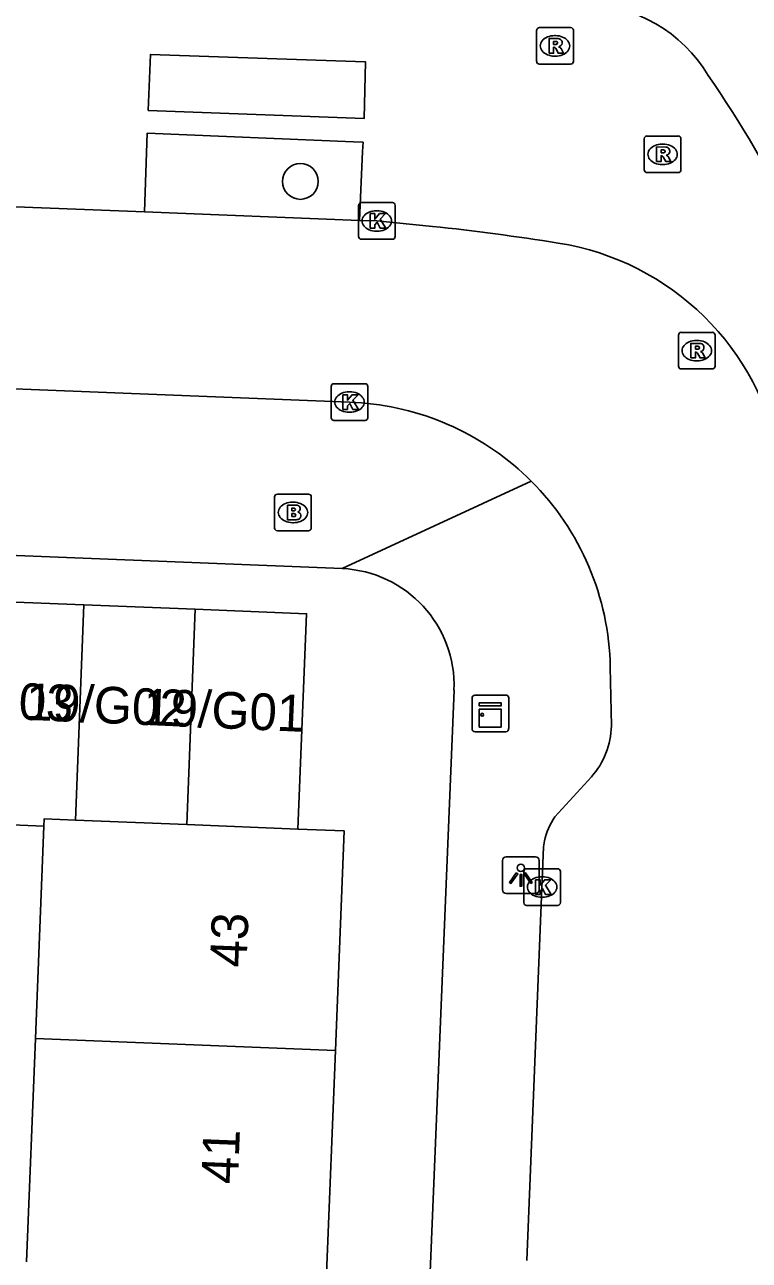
# Model space of a CAD drawing. Extents: x 161355 to 162026, y 386504 to 387459.
# Drawn here: x 161623.15 to 161642.93, y 387194.48 to 387228.21 of the extents above; entities that cross this region are included whole.
import ezdxf

# ---------------------------------------------------------------- set-up
doc = ezdxf.new("R2010")
doc.units = 0
for name, color, linetype in [('IMGEO_Boom', 7, 'Continuous'), ('IMGEO_Brandkraan', 7, 'Continuous'), ('IMGEO_Kast', 7, 'Continuous'), ('IMGEO_Kolk', 7, 'Continuous'), ('IMGEO_Lichtpunt', 7, 'Continuous'), ('IMGEO_Pand', 7, 'Continuous'), ('IMGEO_Pand_nummerreeks', 7, 'Continuous'), ('IMGEO_Rijbaan_lokaal_open', 7, 'Continuous'), ('IMGEO_Rioolput', 7, 'Continuous'), ('IMGEO_Voetpad_open', 7, 'Continuous')]:
    doc.layers.add(name, color=color, linetype=linetype)

msp = doc.modelspace()

# ---------------------------------------------------------------- linework, layer by layer
at = {"layer": 'IMGEO_Boom'}
msp.add_circle((161630.678, 387223.931), 0.489, dxfattribs=at)
at = {"layer": 'IMGEO_Brandkraan'}
for p, q in [((161629.976, 387214.47), (161629.976, 387215.322)), ((161630.051, 387215.396), (161630.903, 387215.396)), ((161630.464, 387215.176), (161630.489, 387215.176)), ((161630.977, 387215.322), (161630.977, 387214.47)), ((161630.487, 387214.616), (161630.462, 387214.616)), ((161630.903, 387214.396), (161630.051, 387214.396))]:
    msp.add_line(p, q, dxfattribs=at)
for points in [[(161629.976, 387214.47), (161629.976, 387215.322)], [(161630.051, 387215.396), (161630.903, 387215.396)], [(161630.977, 387215.322), (161630.977, 387214.47)], [(161630.324, 387215.096), (161630.324, 387214.696), (161630.537, 387214.696)], [(161630.555, 387215.096), (161630.324, 387215.096)], [(161630.503, 387215.015), (161630.449, 387215.015), (161630.449, 387214.939)], [(161630.449, 387214.939), (161630.502, 387214.939)], [(161630.511, 387214.863), (161630.449, 387214.863), (161630.449, 387214.782)], [(161630.449, 387214.782), (161630.511, 387214.782)], [(161630.903, 387214.396), (161630.051, 387214.396)]]:
    msp.add_lwpolyline(points, dxfattribs=at)
for centre, radius, start, end in [((161630.053, 387215.32), 0.0765, 91.552, 178.448), ((161630.053, 387215.32), 0.0765, 91.552, 178.448), ((161630.901, 387215.32), 0.0765, 1.552, 88.448), ((161630.901, 387215.32), 0.0765, 1.552, 88.448), ((161630.504, 387214.977), 0.0379, 267.8285, 90.9355), ((161630.512, 387214.822), 0.0404, 269.8759, 90.5077), ((161630.559, 387214.951), 0.145, 59.4692, 91.5367), ((161630.584, 387214.998), 0.0922, 285.5137, 58.1501), ((161630.589, 387214.806), 0.105, 301.3115, 78.989), ((161630.053, 387214.472), 0.0765, 181.552, 268.448), ((161630.053, 387214.472), 0.0765, 181.552, 268.448), ((161630.543, 387214.947), 0.251, 268.6676, 293.5347), ((161630.901, 387214.472), 0.0765, 271.552, 358.448), ((161630.901, 387214.472), 0.0765, 271.552, 358.448)]:
    msp.add_arc(centre, radius, start, end, dxfattribs=at)
for centre, major_axis, ratio, start_param, end_param in [((161630.463, 387214.896), (-0.387, 0.002), 0.722429, 4.712389, 7.853982), ((161630.488, 387214.896), (-0.39, 0.002), 0.717154, 1.570796, 4.712389)]:
    msp.add_ellipse(centre, major_axis=major_axis, ratio=ratio, start_param=start_param, end_param=end_param, dxfattribs=at)
at = {"layer": 'IMGEO_Kast'}
for p, q in [((161635.364, 387208.987), (161635.364, 387209.828)), ((161635.364, 387209.828), (161635.364, 387208.987)), ((161635.439, 387209.912), (161636.28, 387209.912)), ((161636.28, 387209.912), (161635.439, 387209.912)), ((161636.364, 387209.837), (161636.364, 387208.996)), ((161636.364, 387208.996), (161636.364, 387209.837)), ((161636.289, 387208.912), (161635.448, 387208.912)), ((161635.448, 387208.912), (161636.289, 387208.912))]:
    msp.add_line(p, q, dxfattribs=at)
for points in [[(161635.559, 387209.702), (161636.159, 387209.702), (161636.159, 387209.617), (161635.559, 387209.617), (161635.559, 387209.702)], [(161635.559, 387209.527), (161636.159, 387209.527), (161636.159, 387209.038), (161635.559, 387209.038), (161635.559, 387209.527)]]:
    msp.add_lwpolyline(points, dxfattribs=at)
msp.add_circle((161635.643, 387209.376), 0.0377, dxfattribs=at)
for centre, start, end in [((161635.442, 387209.834), 92.4484, 184.2845), ((161635.442, 387209.834), 92.4484, 184.2845), ((161636.286, 387209.834), 2.4484, 94.2845), ((161636.286, 387209.834), 2.4484, 94.2845), ((161635.442, 387208.99), 182.4484, 274.2845), ((161635.442, 387208.99), 182.4484, 274.2845), ((161636.286, 387208.99), 272.4484, 4.2845), ((161636.286, 387208.99), 272.4484, 4.2845)]:
    msp.add_arc(centre, 0.0779, start, end, dxfattribs=at)
at = {"layer": 'IMGEO_Kolk'}
for p, q in [((161632.265, 387222.426), (161632.265, 387223.278)), ((161632.34, 387223.352), (161633.192, 387223.352)), ((161633.266, 387223.278), (161633.266, 387222.426)), ((161632.753, 387223.132), (161632.778, 387223.132)), ((161632.776, 387222.572), (161632.751, 387222.572)), ((161633.192, 387222.352), (161632.34, 387222.352)), ((161631.518, 387217.483), (161631.518, 387218.335)), ((161631.593, 387218.409), (161632.445, 387218.409)), ((161632.006, 387218.189), (161632.031, 387218.189)), ((161632.519, 387218.335), (161632.519, 387217.483)), ((161632.029, 387217.629), (161632.004, 387217.629)), ((161632.445, 387217.409), (161631.593, 387217.409)), ((161636.776, 387204.246), (161636.776, 387205.098)), ((161636.851, 387205.172), (161637.703, 387205.172)), ((161637.777, 387205.098), (161637.777, 387204.246)), ((161637.264, 387204.952), (161637.289, 387204.952)), ((161637.287, 387204.392), (161637.262, 387204.392)), ((161637.703, 387204.172), (161636.851, 387204.172))]:
    msp.add_line(p, q, dxfattribs=at)
for points in [[(161632.265, 387222.426), (161632.265, 387223.278)], [(161632.34, 387223.352), (161633.192, 387223.352)], [(161633.266, 387223.278), (161633.266, 387222.426)], [(161632.586, 387223.052), (161632.709, 387223.052), (161632.709, 387222.901), (161632.839, 387223.052), (161633.003, 387223.052), (161632.857, 387222.901), (161633.01, 387222.652), (161632.858, 387222.652), (161632.773, 387222.816), (161632.709, 387222.749), (161632.709, 387222.652), (161632.586, 387222.652), (161632.586, 387223.052)], [(161633.192, 387222.352), (161632.34, 387222.352)], [(161631.518, 387217.483), (161631.518, 387218.335)], [(161631.593, 387218.409), (161632.445, 387218.409)], [(161632.519, 387218.335), (161632.519, 387217.483)], [(161631.839, 387218.109), (161631.962, 387218.109), (161631.962, 387217.958), (161632.092, 387218.109), (161632.256, 387218.109), (161632.11, 387217.958), (161632.263, 387217.709), (161632.111, 387217.709), (161632.026, 387217.873), (161631.962, 387217.806), (161631.962, 387217.709), (161631.839, 387217.709), (161631.839, 387218.109)], [(161632.445, 387217.409), (161631.593, 387217.409)], [(161636.776, 387204.246), (161636.776, 387205.098)], [(161636.851, 387205.172), (161637.703, 387205.172)], [(161637.777, 387205.098), (161637.777, 387204.246)], [(161637.097, 387204.872), (161637.22, 387204.872), (161637.22, 387204.721), (161637.35, 387204.872), (161637.514, 387204.872), (161637.368, 387204.721), (161637.521, 387204.472), (161637.369, 387204.472), (161637.284, 387204.636), (161637.22, 387204.569), (161637.22, 387204.472), (161637.097, 387204.472), (161637.097, 387204.872)], [(161637.703, 387204.172), (161636.851, 387204.172)]]:
    msp.add_lwpolyline(points, dxfattribs=at)
for centre, start, end in [((161632.342, 387223.276), 91.552, 178.448), ((161632.342, 387223.276), 91.552, 178.448), ((161633.19, 387223.276), 1.552, 88.448), ((161633.19, 387223.276), 1.552, 88.448), ((161632.342, 387222.428), 181.552, 268.448), ((161632.342, 387222.428), 181.552, 268.448), ((161633.19, 387222.428), 271.552, 358.448), ((161633.19, 387222.428), 271.552, 358.448), ((161631.595, 387218.333), 91.552, 178.448), ((161631.595, 387218.333), 91.552, 178.448), ((161632.443, 387218.333), 1.552, 88.448), ((161632.443, 387218.333), 1.552, 88.448), ((161631.595, 387217.485), 181.552, 268.448), ((161631.595, 387217.485), 181.552, 268.448), ((161632.443, 387217.485), 271.552, 358.448), ((161632.443, 387217.485), 271.552, 358.448), ((161636.853, 387205.096), 91.552, 178.448), ((161636.853, 387205.096), 91.552, 178.448), ((161637.701, 387205.096), 1.552, 88.448), ((161637.701, 387205.096), 1.552, 88.448), ((161636.853, 387204.248), 181.552, 268.448), ((161636.853, 387204.248), 181.552, 268.448), ((161637.701, 387204.248), 271.552, 358.448), ((161637.701, 387204.248), 271.552, 358.448)]:
    msp.add_arc(centre, 0.0765, start, end, dxfattribs=at)
for centre, major_axis, ratio, start_param, end_param in [((161632.752, 387222.852), (-0.387, 0.002), 0.722429, 4.712389, 7.853982), ((161632.777, 387222.852), (-0.39, 0.002), 0.717154, 1.570796, 4.712389), ((161632.005, 387217.909), (-0.387, 0.002), 0.722429, 4.712389, 7.853982), ((161632.03, 387217.909), (-0.39, 0.002), 0.717154, 1.570796, 4.712389), ((161637.263, 387204.672), (-0.387, 0.002), 0.722429, 4.712389, 7.853982), ((161637.288, 387204.672), (-0.39, 0.002), 0.717154, 1.570796, 4.712389)]:
    msp.add_ellipse(centre, major_axis=major_axis, ratio=ratio, start_param=start_param, end_param=end_param, dxfattribs=at)
at = {"layer": 'IMGEO_Lichtpunt'}
for p, q in [((161636.198, 387205.399), (161636.198, 387204.592)), ((161636.198, 387205.399), (161636.198, 387204.592)), ((161637.1, 387205.494), (161636.292, 387205.494)), ((161637.1, 387205.494), (161636.292, 387205.494)), ((161637.194, 387204.592), (161637.194, 387205.399)), ((161637.194, 387204.592), (161637.194, 387205.399)), ((161636.292, 387204.498), (161637.1, 387204.498)), ((161636.292, 387204.498), (161637.1, 387204.498))]:
    msp.add_line(p, q, dxfattribs=at)
for points in [[(161636.572, 387205.063), (161636.611, 387205.035), (161636.423, 387204.773), (161636.385, 387204.8), (161636.572, 387205.063)], [(161636.674, 387205.015), (161636.721, 387205.015), (161636.721, 387204.693), (161636.674, 387204.693), (161636.674, 387205.015)], [(161636.784, 387205.035), (161636.822, 387205.062), (161637.009, 387204.8), (161636.97, 387204.772), (161636.784, 387205.035)]]:
    msp.add_lwpolyline(points, dxfattribs=at)
msp.add_circle((161636.697, 387205.197), 0.0994, dxfattribs=at)
for centre, start, end in [((161636.292, 387205.399), 90, 180), ((161636.292, 387205.399), 90, 180), ((161637.1, 387205.399), 0, 90), ((161637.1, 387205.399), 0, 90), ((161636.292, 387204.592), 180, 270), ((161636.292, 387204.592), 180, 270), ((161637.1, 387204.592), 270, 0), ((161637.1, 387204.592), 270, 360)]:
    msp.add_arc(centre, 0.0946, start, end, dxfattribs=at)
at = {"layer": 'IMGEO_Pand'}
for points in [[(161621.734, 387212.493), (161624.772, 387212.372)], [(161624.772, 387212.372), (161624.538, 387206.497)], [(161624.772, 387212.372), (161627.809, 387212.252)], [(161627.809, 387212.252), (161627.575, 387206.376)], [(161630.613, 387206.255), (161630.846, 387212.131), (161627.809, 387212.252)], [(161623.676, 387206.337), (161621.493, 387206.424)], [(161624.538, 387206.497), (161623.684, 387206.531), (161623.676, 387206.337)], [(161627.575, 387206.376), (161624.538, 387206.497)], [(161630.613, 387206.255), (161627.575, 387206.376)], [(161623.676, 387206.337), (161623.446, 387200.54)], [(161631.638, 387200.215), (161631.876, 387206.205), (161630.613, 387206.255)], [(161623.446, 387200.54), (161623.203, 387194.44)], [(161631.638, 387200.215), (161623.446, 387200.54)], [(161631.396, 387194.115), (161631.638, 387200.215)]]:
    msp.add_lwpolyline(points, dxfattribs=at)
at = {"layer": 'IMGEO_Rijbaan_lokaal_open'}
for points in [[(161621.964, 387223.274), (161626.421, 387223.099)], [(161632.288, 387222.867), (161626.421, 387223.099)], [(161632.288, 387222.867), (161632.766, 387222.852), (161634.283, 387222.704)], [(161632.346, 387217.886), (161632.019, 387217.909), (161611.659, 387218.72)], [(161631.818, 387213.364), (161636.98, 387215.752)], [(161639.137, 387210.673), (161639.169, 387209.071)], [(161634.872, 387210.048), (161631.729, 387133.716)], [(161638.621, 387207.676), (161637.623, 387206.588)], [(161637.343, 387205.929), (161637.319, 387205.77), (161636.861, 387194.478)]]:
    msp.add_lwpolyline(points, dxfattribs=at)
for centre, radius, start, end in [((161627.134, 387155.395), 67.688, 81.0043, 83.93754), ((161636.57, 387215.024), 7.317, 10.0425, 80.9692), ((161631.774, 387210.544), 7.364, 45.0058, 85.5412), ((161631.771, 387210.542), 7.367, 1.0174, 45.0035), ((161631.681, 387210.174), 3.193, 357.7454, 87.5441), ((161636.977, 387209.127), 2.193, 318.5715, 358.5356), ((161639.243, 387205.511), 1.946, 146.3783, 167.5818)]:
    msp.add_arc(centre, radius, start, end, dxfattribs=at)
at = {"layer": 'IMGEO_Rioolput'}
for p, q in [((161637.128, 387227.205), (161637.128, 387228.057)), ((161637.203, 387228.131), (161638.055, 387228.131)), ((161638.129, 387228.057), (161638.129, 387227.205)), ((161637.616, 387227.911), (161637.641, 387227.911)), ((161637.639, 387227.351), (161637.614, 387227.351)), ((161638.055, 387227.131), (161637.203, 387227.131)), ((161640.064, 387224.245), (161640.064, 387225.097)), ((161640.139, 387225.171), (161640.991, 387225.171)), ((161640.552, 387224.951), (161640.577, 387224.951)), ((161641.065, 387225.097), (161641.065, 387224.245)), ((161640.575, 387224.391), (161640.55, 387224.391)), ((161640.991, 387224.171), (161640.139, 387224.171)), ((161640.998, 387218.886), (161640.998, 387219.738)), ((161641.073, 387219.812), (161641.925, 387219.812)), ((161641.486, 387219.592), (161641.511, 387219.592)), ((161641.999, 387219.738), (161641.999, 387218.886)), ((161641.509, 387219.032), (161641.484, 387219.032)), ((161641.925, 387218.812), (161641.073, 387218.812))]:
    msp.add_line(p, q, dxfattribs=at)
for points in [[(161637.128, 387227.205), (161637.128, 387228.057)], [(161637.203, 387228.131), (161638.055, 387228.131)], [(161638.129, 387228.057), (161638.129, 387227.205)], [(161637.717, 387227.829), (161637.465, 387227.831), (161637.465, 387227.431)], [(161637.643, 387227.75), (161637.589, 387227.75), (161637.589, 387227.669)], [(161637.589, 387227.669), (161637.641, 387227.669)], [(161637.465, 387227.431), (161637.589, 387227.431), (161637.589, 387227.593), (161637.6, 387227.593)], [(161637.647, 387227.564), (161637.718, 387227.431), (161637.858, 387227.431), (161637.793, 387227.557)], [(161638.055, 387227.131), (161637.203, 387227.131)], [(161640.064, 387224.245), (161640.064, 387225.097)], [(161640.139, 387225.171), (161640.991, 387225.171)], [(161641.065, 387225.097), (161641.065, 387224.245)], [(161640.653, 387224.869), (161640.401, 387224.871), (161640.401, 387224.471)], [(161640.401, 387224.471), (161640.525, 387224.471), (161640.525, 387224.633), (161640.536, 387224.633)], [(161640.579, 387224.79), (161640.525, 387224.79), (161640.525, 387224.709)], [(161640.525, 387224.709), (161640.577, 387224.709)], [(161640.583, 387224.604), (161640.654, 387224.471), (161640.794, 387224.471), (161640.729, 387224.597)], [(161640.991, 387224.171), (161640.139, 387224.171)], [(161640.998, 387218.886), (161640.998, 387219.738)], [(161641.073, 387219.812), (161641.925, 387219.812)], [(161641.587, 387219.51), (161641.335, 387219.512), (161641.335, 387219.112)], [(161641.999, 387219.738), (161641.999, 387218.886)], [(161641.335, 387219.112), (161641.459, 387219.112), (161641.459, 387219.274), (161641.47, 387219.274)], [(161641.513, 387219.431), (161641.459, 387219.431), (161641.459, 387219.35)], [(161641.459, 387219.35), (161641.511, 387219.35)], [(161641.517, 387219.245), (161641.588, 387219.112), (161641.728, 387219.112), (161641.663, 387219.238)], [(161641.925, 387218.812), (161641.073, 387218.812)]]:
    msp.add_lwpolyline(points, dxfattribs=at)
for centre, radius, start, end in [((161637.205, 387228.055), 0.0765, 91.552, 178.448), ((161637.205, 387228.055), 0.0765, 91.552, 178.448), ((161638.053, 387228.055), 0.0765, 1.552, 88.448), ((161638.053, 387228.055), 0.0765, 1.552, 88.448), ((161637.625, 387227.858), 0.19, 274.7715, 282.9687), ((161637.649, 387227.654), 0.0964, 77.0061, 93.1865), ((161637.663, 387227.711), 0.0378, 276.6634, 79.6772), ((161637.716, 387227.719), 0.109, 350.3612, 89.416), ((161637.714, 387227.719), 0.112, 277.5842, 350.9817), ((161637.698, 387227.504), 0.108, 29.5134, 73.7905), ((161637.599, 387227.54), 0.0533, 26.0293, 88.6989), ((161637.205, 387227.207), 0.0765, 181.552, 268.448), ((161637.205, 387227.207), 0.0765, 181.552, 268.448), ((161638.053, 387227.207), 0.0765, 271.552, 358.448), ((161638.053, 387227.207), 0.0765, 271.552, 358.448), ((161640.141, 387225.095), 0.0765, 91.552, 178.448), ((161640.141, 387225.095), 0.0765, 91.552, 178.448), ((161640.989, 387225.095), 0.0765, 1.552, 88.448), ((161640.989, 387225.095), 0.0765, 1.552, 88.448), ((161640.535, 387224.58), 0.0533, 26.0293, 88.6989), ((161640.561, 387224.898), 0.19, 274.7715, 282.9687), ((161640.585, 387224.694), 0.0964, 77.0061, 93.1865), ((161640.599, 387224.751), 0.0378, 276.6634, 79.6772), ((161640.652, 387224.759), 0.109, 350.3612, 89.416), ((161640.65, 387224.759), 0.112, 277.5842, 350.9817), ((161640.634, 387224.544), 0.108, 29.5134, 73.7905), ((161640.141, 387224.247), 0.0765, 181.552, 268.448), ((161640.141, 387224.247), 0.0765, 181.552, 268.448), ((161640.989, 387224.247), 0.0765, 271.552, 358.448), ((161640.989, 387224.247), 0.0765, 271.552, 358.448), ((161641.075, 387219.736), 0.0765, 91.552, 178.448), ((161641.075, 387219.736), 0.0765, 91.552, 178.448), ((161641.586, 387219.4), 0.109, 350.3612, 89.416), ((161641.923, 387219.736), 0.0765, 1.552, 88.448), ((161641.923, 387219.736), 0.0765, 1.552, 88.448), ((161641.469, 387219.221), 0.0533, 26.0293, 88.6989), ((161641.495, 387219.539), 0.19, 274.7715, 282.9687), ((161641.519, 387219.335), 0.0964, 77.0061, 93.1865), ((161641.533, 387219.392), 0.0378, 276.6634, 79.6772), ((161641.584, 387219.4), 0.112, 277.5842, 350.9817), ((161641.568, 387219.185), 0.108, 29.5134, 73.7905), ((161641.075, 387218.888), 0.0765, 181.552, 268.448), ((161641.075, 387218.888), 0.0765, 181.552, 268.448), ((161641.923, 387218.888), 0.0765, 271.552, 358.448), ((161641.923, 387218.888), 0.0765, 271.552, 358.448)]:
    msp.add_arc(centre, radius, start, end, dxfattribs=at)
for centre, major_axis, ratio, start_param, end_param in [((161637.615, 387227.631), (-0.387, 0.002), 0.722429, 4.712389, 7.853982), ((161637.64, 387227.631), (-0.39, 0.002), 0.717154, 1.570796, 4.712389), ((161640.551, 387224.671), (-0.387, 0.002), 0.722429, 4.712389, 7.853982), ((161640.576, 387224.671), (-0.39, 0.002), 0.717154, 1.570796, 4.712389), ((161641.485, 387219.312), (-0.387, 0.002), 0.722429, 4.712389, 7.853982), ((161641.51, 387219.312), (-0.39, 0.002), 0.717154, 1.570796, 4.712389)]:
    msp.add_ellipse(centre, major_axis=major_axis, ratio=ratio, start_param=start_param, end_param=end_param, dxfattribs=at)
at = {"layer": 'IMGEO_Voetpad_open'}
for points in [[(161626.525, 387225.867), (161626.586, 387227.399), (161630.037, 387227.279), (161632.457, 387227.194), (161632.424, 387225.652), (161626.525, 387225.867)], [(161626.421, 387223.099), (161626.496, 387225.246), (161632.131, 387225.011), (161632.388, 387225), (161632.376, 387224.746), (161632.288, 387222.867)], [(161612.661, 387214.128), (161631.818, 387213.364)]]:
    msp.add_lwpolyline(points, dxfattribs=at)
for centre, radius, start, end in [((161638.345, 387224.734), 4.048, 31.0628, 88.6675), ((161617.372, 387209.873), 29.742, 16.6219, 34.7408)]:
    msp.add_arc(centre, radius, start, end, dxfattribs=at)

# ---------------------------------------------------------------- texts
at = {"layer": 'IMGEO_Pand_nummerreeks'}
for s, rotation, p in [('19/G03', 357.4937, (161620.078, 387209.374)), ('19/G02', 357.4937, (161623.166, 387209.239)), ('19/G01', 357.4937, (161626.376, 387209.099)), ('43', 87.7242, (161629.206, 387202.467)), ('41', 87.7242, (161628.971, 387196.553))]:
    msp.add_text(s, height=1, rotation=rotation, dxfattribs=at).set_placement(p)

doc.saveas('drawing.dxf')
